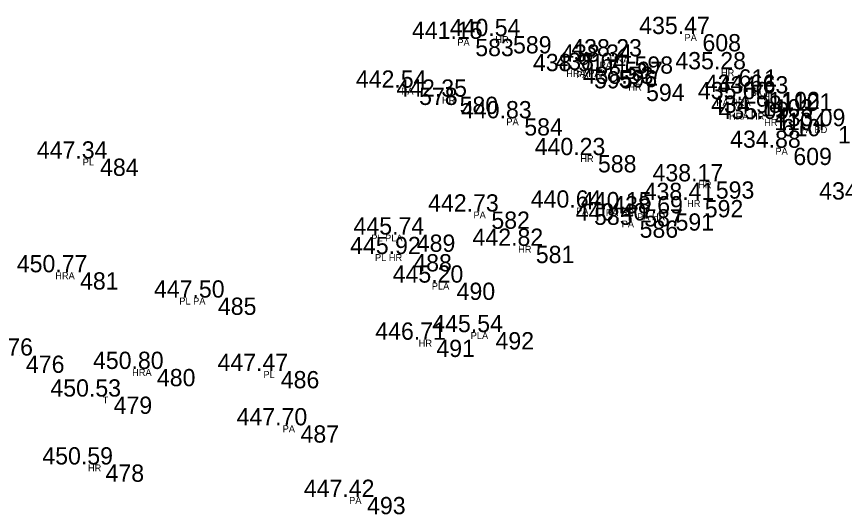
# Model space of a CAD drawing. Extents: x -639390 to -639075, y -1138747 to -1138358.
# Drawn here: x -639130.26 to -639094.29, y -1138747.34 to -1138725.71 of the extents above; entities that cross this region are included whole.
import ezdxf

# ---------------------------------------------------------------- set-up
doc = ezdxf.new("R2010")
doc.units = 0
for name, color, linetype in [('Vrstva 11', 7, 'Continuous'), ('Vrstva 12', 7, 'Continuous'), ('Vrstva 13', 7, 'Continuous'), ('Vrstva 57', 7, 'Continuous')]:
    doc.layers.add(name, color=color, linetype=linetype)

msp = doc.modelspace()

# ---------------------------------------------------------------- linework, layer by layer
at = {"layer": 'Vrstva 11'}
for p, q in [((-639108.97, -1138726.56), (-639108.97, -1138726.56)), ((-639100.74, -1138726.47), (-639100.74, -1138726.47)), ((-639110.61, -1138726.68), (-639110.61, -1138726.68)), ((-639104.13, -1138727.67), (-639104.13, -1138727.67)), ((-639103.69, -1138727.44), (-639103.69, -1138727.44)), ((-639105.45, -1138728.08), (-639105.45, -1138728.08)), ((-639104.38, -1138728.03), (-639104.38, -1138728.03)), ((-639099.17, -1138728), (-639099.17, -1138728)), ((-639113.05, -1138728.8), (-639113.05, -1138728.8)), ((-639103.19, -1138728.63), (-639103.19, -1138728.63)), ((-639111.29, -1138729.19), (-639111.29, -1138729.19)), ((-639097.87, -1138728.98), (-639097.87, -1138728.98)), ((-639097.33, -1138729.05), (-639097.33, -1138729.05)), ((-639098.16, -1138729.3), (-639098.16, -1138729.3)), ((-639097.62, -1138729.89), (-639097.62, -1138729.89)), ((-639108.48, -1138730.13), (-639108.48, -1138730.13)), ((-639097.29, -1138730.16), (-639097.29, -1138730.16)), ((-639094.85, -1138730.47), (-639094.85, -1138730.47)), ((-639096.79, -1138731.41), (-639096.79, -1138731.41)), ((-639126.91, -1138731.88), (-639126.91, -1138731.88)), ((-639105.28, -1138731.73), (-639105.28, -1138731.73)), ((-639100.16, -1138732.87), (-639100.16, -1138732.87)), ((-639100.64, -1138733.68), (-639100.64, -1138733.68)), ((-639109.91, -1138734.18), (-639109.91, -1138734.18)), ((-639105.45, -1138734.01), (-639105.45, -1138734.01)), ((-639103.27, -1138734.08), (-639103.27, -1138734.08)), ((-639103.47, -1138734.57), (-639103.47, -1138734.57)), ((-639101.91, -1138734.26), (-639101.91, -1138734.26)), ((-639113.15, -1138735.18), (-639113.15, -1138735.18)), ((-639107.98, -1138735.67), (-639107.98, -1138735.67)), ((-639113.3, -1138736.03), (-639113.3, -1138736.03)), ((-639127.78, -1138736.82), (-639127.78, -1138736.82)), ((-639111.42, -1138737.27), (-639111.42, -1138737.27)), ((-639121.79, -1138737.92), (-639121.79, -1138737.92)), ((-639109.73, -1138739.42), (-639109.73, -1138739.42)), ((-639112.3, -1138739.75), (-639112.3, -1138739.75)), ((-639130.13, -1138740.44), (-639130.13, -1138740.44)), ((-639124.44, -1138741.02), (-639124.44, -1138741.02)), ((-639119.06, -1138741.11), (-639119.06, -1138741.11)), ((-639126.32, -1138742.22), (-639126.32, -1138742.22)), ((-639118.2, -1138743.47), (-639118.2, -1138743.47)), ((-639126.67, -1138745.17), (-639126.67, -1138745.17)), ((-639115.31, -1138746.58), (-639115.31, -1138746.58))]:
    msp.add_line(p, q, dxfattribs=at)

# ---------------------------------------------------------------- texts
at = {"layer": 'Vrstva 12'}
for s, p in [('441.15 ', (-639113.08, -1138726.68)), ('440.54 ', (-639111.439, -1138726.56)), ('435.47 ', (-639103.209, -1138726.47)), ('438.34 ', (-639106.599, -1138727.67)), ('438.23 ', (-639106.159, -1138727.44)), ('438.91 ', (-639107.825, -1138728.08)), ('438.64 ', (-639106.849, -1138728.03)), ('435.28 ', (-639101.639, -1138728)), ('442.54 ', (-639115.519, -1138728.8)), ('438.53 ', (-639105.659, -1138728.63)), ('442.35 ', (-639113.76, -1138729.19)), ('434.66 ', (-639100.356, -1138728.98)), ('434.63 ', (-639099.799, -1138729.05)), ('435.00 ', (-639100.659, -1138729.3)), ('434.98 ', (-639100.089, -1138729.89)), ('440.83 ', (-639110.949, -1138730.13)), ('435.09 ', (-639099.759, -1138730.16)), ('433.09 ', (-639097.319, -1138730.47)), ('440.23 ', (-639107.749, -1138731.73)), ('434.88 ', (-639099.259, -1138731.41)), ('447.34 ', (-639129.379, -1138731.88)), ('438.17 ', (-639102.629, -1138732.87)), ('438.41 ', (-639103.015, -1138733.68)), ('434.18 ', (-639095.389, -1138733.66)), ('442.73 ', (-639112.379, -1138734.18)), ('440.64 ', (-639107.919, -1138734.01)), ('440.15 ', (-639105.74, -1138734.08)), ('438.69 ', (-639104.379, -1138734.26)), ('440.40 ', (-639105.969, -1138734.57)), ('445.74 ', (-639115.619, -1138735.18)), ('442.82 ', (-639110.449, -1138735.67)), ('445.92 ', (-639115.769, -1138736.03)), ('450.77 ', (-639130.249, -1138736.82)), ('445.20 ', (-639113.919, -1138737.27)), ('447.50 ', (-639124.289, -1138737.92)), ('445.54 ', (-639112.199, -1138739.42)), ('446.71 ', (-639114.675, -1138739.75)), ('450.76 ', (-639132.616, -1138740.44)), ('450.80 ', (-639126.939, -1138741.02)), ('447.47 ', (-639121.529, -1138741.11)), ('450.53 ', (-639128.789, -1138742.22)), ('447.70 ', (-639120.699, -1138743.47)), ('450.59 ', (-639129.139, -1138745.17)), ('447.42 ', (-639117.779, -1138746.58))]:
    msp.add_text(s, height=0.75, dxfattribs=at).set_placement(p)
at = {"layer": 'Vrstva 13'}
for s, p in [(' 583', (-639110.61, -1138727.43)), (' 589', (-639108.97, -1138727.31)), (' 608', (-639100.74, -1138727.22)), (' 597', (-639104.13, -1138728.42)), (' 598', (-639103.69, -1138728.19)), (' 595', (-639105.45, -1138728.83)), (' 596', (-639104.38, -1138728.78)), (' 611', (-639099.17, -1138728.75)), (' 578', (-639113.05, -1138729.55)), (' 594', (-639103.19, -1138729.38)), (' 580', (-639111.29, -1138729.94)), (' 1102', (-639097.87, -1138729.73)), (' 1101', (-639097.33, -1138729.8)), (' 1103', (-639098.16, -1138730.05)), (' 1104', (-639097.62, -1138730.64)), (' 584', (-639108.48, -1138730.88)), (' 610', (-639097.29, -1138730.91)), (' 1107', (-639094.85, -1138731.22)), (' 609', (-639096.79, -1138732.16)), (' 484', (-639126.91, -1138732.63)), (' 588', (-639105.28, -1138732.48)), (' 593', (-639100.16, -1138733.62)), (' 592', (-639100.64, -1138734.43)), (' 582', (-639109.91, -1138734.93)), (' 585', (-639105.45, -1138734.76)), (' 587', (-639103.27, -1138734.83)), (' 586', (-639103.47, -1138735.32)), (' 591', (-639101.91, -1138735.01)), (' 489', (-639113.15, -1138735.93)), (' 581', (-639107.98, -1138736.42)), (' 488', (-639113.3, -1138736.78)), (' 481', (-639127.78, -1138737.57)), (' 490', (-639111.42, -1138738.02)), (' 485', (-639121.79, -1138738.67)), (' 492', (-639109.73, -1138740.17)), (' 491', (-639112.3, -1138740.5)), (' 476', (-639130.13, -1138741.19)), (' 480', (-639124.44, -1138741.77)), (' 486', (-639119.06, -1138741.86)), (' 479', (-639126.32, -1138742.97)), (' 487', (-639118.2, -1138744.22)), (' 478', (-639126.67, -1138745.92)), (' 493', (-639115.31, -1138747.33))]:
    msp.add_text(s, height=0.75, dxfattribs=at).set_placement(p)
at = {"layer": 'Vrstva 57'}
for s, p in [('HR', (-639109.459, -1138726.86)), ('PA', (-639101.24, -1138726.77)), ('PA', (-639111.11, -1138726.98)), ('PAA', (-639104.93, -1138727.97)), ('HRA', (-639104.49, -1138727.74)), ('HRA PAA', (-639106.38, -1138728.33)), ('PA', (-639105.95, -1138728.38)), ('HR', (-639099.659, -1138728.3)), ('PA', (-639113.55, -1138729.1)), ('HR', (-639103.679, -1138728.93)), ('HR', (-639111.779, -1138729.49)), ('PA', (-639098.37, -1138729.28)), ('HR', (-639097.819, -1138729.35)), ('PA HRA', (-639099.86, -1138729.6)), ('HRA HR', (-639099.309, -1138730.19)), ('PA', (-639108.98, -1138730.43)), ('HR', (-639097.779, -1138730.46)), ('PA BD', (-639096.241, -1138730.77)), ('PA', (-639097.29, -1138731.71)), ('PL', (-639127.385, -1138732.18)), ('HR', (-639105.769, -1138732.03)), ('HR', (-639100.649, -1138733.17)), ('HR', (-639101.129, -1138733.98)), ('PA', (-639110.41, -1138734.48)), ('PA', (-639105.95, -1138734.31)), ('PA HR', (-639104.659, -1138734.38)), ('PA', (-639103.97, -1138734.87)), ('PA HR', (-639103.299, -1138734.56)), ('PL PLA', (-639114.85, -1138735.48)), ('HR', (-639108.469, -1138735.97)), ('PL HR', (-639114.689, -1138736.33)), ('HRA', (-639128.58, -1138737.12)), ('PLA', (-639112.22, -1138737.57)), ('PL PA', (-639123.19, -1138738.22)), ('PLA', (-639110.53, -1138739.72)), ('HR', (-639112.789, -1138740.05)), ('HRA', (-639125.24, -1138741.32)), ('PL', (-639119.535, -1138741.41)), ('T', (-639126.52, -1138742.52)), ('PA', (-639118.7, -1138743.77)), ('HR', (-639127.159, -1138745.47)), ('PA', (-639115.81, -1138746.88))]:
    msp.add_text(s, height=0.3, dxfattribs=at).set_placement(p)

doc.saveas('drawing.dxf')
